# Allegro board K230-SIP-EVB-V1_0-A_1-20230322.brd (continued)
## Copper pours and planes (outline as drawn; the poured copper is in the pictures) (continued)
VDD_1V8 on POWER04: 65.21,78.17 50.04,93.34 32.38,93.34 31.75,92.71 31.75,89.28 31.62,89.15 13.21,89.15 7.75,83.69 7.75,49.02 8.38,48.39 23.62,48.39 23.88,48.13 23.88,33.4 23.62,33.15 16,33.15 14.86,32 14.86,16.64 15.62,15.88 32,15.88 35.43,19.3 35.43,43.05 35.69,43.31 74.8,43.31 75.06,43.05 75.06,8.89 71.63,5.46 7.75,5.46 0.89,12.32 0.89,108.71 1.4,109.22 7.87,109.22 8,109.35 8,135.38 8.13,135.51 71.25,135.51 74.3,132.46 74.3,78.49 73.98,78.17
VDD_3V3 on TOP: 8.64,91.57 8.76,91.69 9.65,91.69 9.78,91.57 9.78,89.92 9.65,89.79 8.76,89.79 8.64,89.92
VDD_3V3 on TOP: 21.72,28.7 21.72,31.24 22.1,31.62 22.1,32.13 22.23,32.26 23.11,32.26 23.24,32.13 23.24,30.86 22.86,30.48 22.86,28.7 22.73,28.57 21.84,28.57
VDD_3V3 on TOP: 17.02,130.94 17.02,127.38 17.14,127.25 19.56,127.25 19.68,127.13 19.68,125.09 19.56,124.97 14.61,124.97 14.48,125.09 14.48,125.98 15.49,127 15.49,130.94 15.62,131.06 16.89,131.06
VDD_3V3 on TOP: 30.61,45.97 30.86,46.23 30.86,46.74 30.99,46.86 32,46.86 32.13,46.74 32.13,45.21 31.75,44.83 31.75,42.93 31.62,42.8 30.73,42.8 30.61,42.93
VDD_3V3 on TOP: 28.57,28.7 28.57,31.24 28.96,31.62 28.96,32.13 29.08,32.26 29.59,32.26 29.72,32.13 29.72,28.7 29.59,28.57 28.7,28.57
VDD_3V3 on TOP: 46.74,131.32 51.18,131.32 51.31,131.19 51.31,129.16 51.18,129.03 46.86,129.03 46.61,129.29 46.61,131.19
VDD_3V3 on TOP: 44.07,46.23 44.07,46.74 44.2,46.86 45.09,46.86 45.21,46.74 45.21,45.47 44.83,45.09 44.83,43.18 44.7,43.05 43.69,43.05 43.56,43.18 43.56,45.72
VDD_3V3 on TOP: 18.8,19.81 18.92,19.68 18.92,17.91 18.8,17.78 15.37,17.78 15.24,17.91 15.24,19.68 15.37,19.81
VDD_3V3 on BOTTOM: 66.8,88.14 70.61,88.14 70.74,88.01 70.74,86.74 70.61,86.61 66.8,86.61 66.67,86.74 66.67,88.01
VDD_3V3 on BOTTOM: 56.45,131.06 56.45,119.32 60.58,115.19 60.58,112.27 60.33,112.01 55.5,112.01 53.09,114.43 34.42,114.43 34.16,114.68 34.16,119.76 34.42,120.02 49.02,120.02 49.4,120.4 49.4,131.06 49.53,131.19 56.32,131.19
VDD_3V3 on ART03: 78.74,91.82 78.74,73.03 78.61,72.9 71.25,72.9 71.12,73.03 71.12,78.11 61.47,87.76 61.47,98.81 58.93,101.35 58.93,113.67 59.05,113.79 71.12,113.79 71.25,113.67 71.25,99.31
VDD_3V3 on ART03: 9.14,89.79 10.99,91.63 10.99,100.65 26.67,116.33 35.69,116.33 35.81,116.46 35.81,127.13 35.69,127.25 17.91,127.25 17.78,127.13 17.78,119.13 2.41,103.76 2.41,89.92 2.54,89.79
VDD_3V3 on POWER04: 16.26,17.53 16,17.78 16,31.5 16.64,32.13 24.51,32.13 24.89,32.51 24.89,47.88 26.16,49.15 26.16,54.86 26.29,54.99 69.34,54.99 71.37,57.02 71.37,76.45 71.88,76.96 78.49,76.96 78.87,76.58 78.87,48.77 74.3,44.2 34.92,44.2 34.29,43.56 34.29,20.45 31.37,17.53
VDD_3V3_K210 on TOP: 10.79,25.02 10.79,24 10.67,23.88 8.51,23.88 8.38,24 8.38,25.02 8.51,25.15 10.67,25.15
VDD_3V3_USB on TOP: 18.8,17.53 18.92,17.4 18.92,15.75 18.8,15.62 15.11,15.62 14.99,15.75 14.99,17.4 15.11,17.53
VDD_5V on TOP (solid shape): 16.64,49.28 16.64,47.88 16.51,47.75 16.51,46.61 16.51,46.48 16.38,46.35 16.38,44.7 16.26,44.58 14.35,44.58 14.22,44.7 14.22,47.62 16,49.4 16.51,49.4
VDD_5V on TOP (solid shape): 46.23,27.81 46.23,26.42 46.1,26.29 46.1,25.15 46.1,25.02 45.97,24.89 45.97,23.37 45.85,23.24 44.07,23.24 43.81,23.5 43.81,26.16 45.59,27.94 46.1,27.94
VDD_5V on TOP (solid shape): 67.56,32.13 67.56,30.23 67.56,29.21 67.18,28.83 67.18,28.58 67.18,28.58 67.18,26.8 67.18,26.8 67.18,26.42 67.06,26.29 64.01,26.29 63.88,26.42 63.88,29.08 64.01,29.21 65.53,29.21 65.79,29.46 65.79,31.11 66.29,31.62 66.29,32.13 66.42,32.26 67.44,32.26
VDD_5V on TOP: 52.83,26.54 52.96,26.67 54.61,26.67 54.74,26.54 54.74,26.29 54.86,26.16 55.63,26.16 55.75,26.04 55.75,23.24 55.63,23.11 51.05,23.11 50.93,23.24 50.93,24 51.05,24.13 52.7,24.13 52.83,24.26
VDD_5V on TOP: 35.18,18.67 35.31,18.54 35.31,15.37 35.18,15.24 31.75,15.24 31.62,15.37 31.62,18.54 31.75,18.67
VDD_5V on TOP: 53.85,132.33 56.26,132.33 56.39,132.21 56.39,130.3 56.13,130.05 53.85,130.05 53.72,130.18 53.72,132.21
VDD_5V on TOP: 65.79,65.41 65.91,65.28 65.91,62.61 65.79,62.48 64.01,62.48 63.88,62.61 63.88,64.01 65.28,65.41
VDD_5V on TOP: 25.53,22.61 25.65,22.73 26.67,22.73 26.8,22.61 30.86,22.61 30.99,22.48 30.99,20.83 30.86,20.7 26.92,20.7 25.53,22.1
VDD_5V on TOP: 64.26,46.74 64.26,47.5 64.14,47.62 63.88,47.62 63.63,47.37 63.63,42.16 63.75,42.04 65.28,42.04 65.41,42.16 65.41,45.59
VDD_5V on TOP: 53.47,47.75 53.47,48.51 53.34,48.64 53.09,48.64 52.83,48.39 52.83,43.18 52.96,43.05 54.48,43.05 54.61,43.18 54.61,46.61
VDD_5V on TOP: 16.89,29.21 18.41,29.21 18.54,29.08 18.54,27.81 18.41,27.69 16.89,27.69 16.76,27.81 16.76,29.08
VDD_5V on BOTTOM: 1.4,7.49 1.14,7.75 1.14,34.16 2.16,35.18 8.51,35.18 10.16,36.83 10.16,52.32 10.41,52.58 18.03,52.58 18.16,52.45 18.16,31.75 18.86,31.05 51.37,31.05 51.94,31.62 51.94,46.35 52.07,46.48 66.29,46.48 67.06,47.24 67.06,55.5 63.88,58.67 63.88,64.64 64.01,64.77 68.83,64.77 71.69,67.63 71.69,88.27 69.6,90.36 69.6,106.68 64.77,111.51 64.77,124.33 61.09,128.02 61.09,129.92 61.21,130.05 63.85,130.05 67.28,126.62 67.28,112.81 72.07,108.01 72.07,93.92 77.09,88.9 77.09,78.99 76.71,78.61 76.71,66.17 72.52,61.98 72.52,40.89 68.01,36.39 68.01,28.13 60.33,20.45 48.9,20.45 43.43,14.99 32.64,14.99 32.38,14.73 32.38,7.62 32.26,7.49
VDD_5V on BOTTOM: 9.78,112.39 10.67,111.51 10.67,111 10.54,110.87 9.27,110.87 8.26,111.89 8.26,117.73 8.38,117.86 9.65,117.86 9.78,117.73
VDD_5V on ART03: 61.91,128.59 61.59,128.27 51.94,128.27 46.35,133.86 22.61,133.86 13.59,124.84 13.59,116.2 13.21,115.82 6.22,115.82 5.97,116.08 5.97,128.14 16.26,138.43 60.2,138.43 61.91,136.72
VDD_5V_O on TOP: 46.1,132.97 46.1,134.75 47.75,136.4 54.61,136.4 56.39,134.62 56.39,133.22 56.26,133.1 52.32,133.1 51.69,132.46 46.61,132.46
VDD_5V_O on TOP: 7.11,90.68 6.99,90.81 5.84,90.81 3.68,92.96 3.68,106.68 4.19,107.19 8,107.19 10.41,109.6 10.41,122.68 10.29,122.81 7.62,122.81 7.49,122.68 7.49,112.14 5.71,110.36 2.16,110.36 1.4,109.6 1.4,90.3 2.92,88.77 6.99,88.77 7.11,88.9
VDD_5V_O on BOTTOM: 51.69,138.3 51.69,134.49 51.56,134.37 49.15,134.37 49.02,134.49 49.02,136.4 48.9,136.53 35.94,136.53 27.81,128.4 9.91,128.4 8.26,126.75 8.26,119.51 8.13,119.38 4.45,119.38 4.32,119.51 4.32,128.4 8.89,132.97 26.67,132.97 32.38,138.68 51.31,138.68
(no net) on TOP: 44.45,35.05 44.45,38.35 44.07,38.73 41.02,38.73 40.89,38.86 40.89,40.13 41.02,40.26 46.86,40.26 46.99,40.13 46.99,35.05 46.86,34.92 44.58,34.92
(no net) on TOP: 46.86,23.24 46.74,23.37 46.74,25.02 46.61,25.15 46.61,27.69 46.86,27.94 46.86,29.21 46.74,29.34 44.2,29.34 44.07,29.46 44.07,30.23 44.2,30.35 47.37,30.35 47.5,30.48 47.5,40.89 47.62,41.02 55.88,41.02 56.01,40.89 56.01,38.48 55.88,38.35 53.85,38.35 53.47,38.73 50.16,38.73 50.04,38.61 50.04,29.34 49.53,28.83 49.53,24.38 48.39,23.24
(no net) on TOP: 12.7,56.01 12.7,57.15 12.57,57.28 11.43,57.28 11.3,57.4 11.3,58.8 11.43,58.93 14.35,58.93 14.48,58.8 14.48,56.01 14.35,55.88 12.83,55.88
(no net) on TOP: 14.86,56.52 14.86,59.82 14.48,60.2 11.43,60.2 11.3,60.33 11.3,61.85 11.43,61.98 17.27,61.98 17.4,61.85 17.4,56.52 17.27,56.39 14.99,56.39
(no net) on TOP: 43.05,32.26 43.05,33.02 42.93,33.15 42.42,33.15 42.29,33.27 42.29,34.04 42.42,34.16 43.81,34.16 43.94,34.04 43.94,32.26 43.81,32.13 43.18,32.13
(no net) on TOP: 13.46,53.72 13.46,54.48 13.34,54.61 12.83,54.61 12.7,54.74 12.7,55.5 12.83,55.63 14.22,55.63 14.35,55.5 14.35,53.72 14.22,53.59 13.59,53.59
(no net) on TOP: 14.73,54.99 14.86,55.12 17.4,55.12 17.53,54.99 17.53,53.09 17.4,52.96 16.26,52.96 15.62,53.59 14.86,53.59 14.73,53.72
(no net) on TOP: 11.18,57.02 11.81,57.02 11.94,56.9 11.94,53.85 11.81,53.72 6.86,53.72 6.73,53.85 6.73,58.8 6.86,58.93 10.79,58.93 10.92,58.8 10.92,57.28
(no net) on TOP: 67.94,32.51 64.9,32.51 64.77,32.64 64.77,33.4 64.9,33.53 67.94,33.53 68.07,33.66 68.07,36.58 68.2,36.7 70.23,36.7 70.36,36.58 70.36,26.42 70.23,26.29 68.58,26.29 68.45,26.42 68.45,28.96 68.07,29.34 68.07,32.38
(no net) on TOP: 16.51,49.4 16.64,49.28 16.64,47.88 16.51,47.75 16.51,46.48 16.38,46.35 16.38,44.7 16.26,44.58 14.35,44.58 14.22,44.7 14.22,47.62 16,49.4
(no net) on TOP: 63.25,38.86 63.12,38.99 63.12,40.77 63.25,40.89 67.44,40.89 67.56,40.77 67.56,38.99 67.44,38.86
(no net) on TOP: 68.07,38.1 68.07,40.77 68.2,40.89 75.82,40.89 75.95,40.77 75.95,38.1 75.82,37.97 68.2,37.97
(no net) on TOP: 40.77,35.56 41.4,35.56 41.53,35.43 41.53,32.26 41.4,32.13 39.62,32.13 39.5,32.26 39.5,36.45 39.62,36.58 40.51,36.58 40.64,36.45 40.64,35.69
(no net) on TOP: 42.29,34.54 42.29,35.69 42.16,35.81 41.02,35.81 40.89,35.94 40.89,37.34 41.02,37.47 43.94,37.47 44.07,37.34 44.07,34.54 43.94,34.42 42.42,34.42
(no net) on TOP: 67.56,33.91 67.44,33.78 66.42,33.78 66.29,33.91 66.29,34.92 65.91,35.31 65.91,38.48 66.04,38.61 67.44,38.61 67.56,38.48
(no net) on TOP: 63.88,29.08 64.01,29.21 65.53,29.21 65.79,29.46 65.79,31.11 66.29,31.62 66.29,32.13 66.42,32.26 67.44,32.26 67.56,32.13 67.56,29.21 67.18,28.83 67.18,26.42 67.06,26.29 64.01,26.29 63.88,26.42
(no net) on TOP: 44.32,33.53 44.45,33.66 46.99,33.66 47.12,33.53 47.12,31.62 46.99,31.5 45.85,31.5 45.21,32.13 44.45,32.13 44.32,32.26
(no net) on TOP: 46.1,27.94 46.23,27.81 46.23,26.42 46.1,26.29 46.1,25.02 45.97,24.89 45.97,23.37 45.85,23.24 44.07,23.24 43.81,23.5 43.81,26.16 45.59,27.94
INA226_0V8+ on TOP (solid shape): 17.4,61.85 17.4,60.07 17.4,60.07 17.4,59.05 17.4,59.05 17.4,58.8 17.4,58.8 17.4,57.78 17.4,57.78 17.4,56.52 17.27,56.39 14.99,56.39 14.86,56.52 14.86,59.82 14.48,60.2 11.43,60.2 11.3,60.33 11.3,61.85 11.43,61.98 17.27,61.98
INA226_0V8- on TOP (solid shape): 14.48,58.8 14.48,56.01 14.35,55.88 12.83,55.88 12.7,56.01 12.7,57.15 12.57,57.28 11.43,57.28 11.3,57.4 11.3,58.8 11.43,58.93 14.35,58.93
INA226_1V8IO+ on TOP: 66.29,75.82 66.04,75.56 66.04,71.88 65.91,71.75 63.5,71.75 63.37,71.88 63.37,78.61 63.5,78.74 66.17,78.74 66.29,78.61
INA226_1V8IO- on TOP: 61.85,69.72 61.72,69.85 61.72,74.55 60.45,75.82 60.45,77.72 60.58,77.85 61.98,77.85 62.1,77.72 62.1,76.07 63.12,75.06 63.12,69.85 62.99,69.72
INA226_AVDDMIPI+ on TOP: 16,33.78 15.37,33.78 15.24,33.91 15.24,34.8 14.86,35.18 14.86,37.34 14.48,37.72 14.48,39.37 14.61,39.5 16.38,39.5 16.51,39.37 16.51,37.85 16.13,37.47 16.13,33.91
INA226_AVDDMIPI- on TOP: 16.51,42.8 16.51,40.89 16.38,40.77 14.61,40.77 14.22,41.15 13.34,41.15 13.21,41.27 13.21,42.8 13.34,42.93 16.38,42.93
INA226_CORE0+ on TOP (solid shape): 46.99,40.13 46.99,38.61 46.99,37.59 46.99,37.34 46.99,36.32 46.99,35.05 46.86,34.92 44.58,34.92 44.45,35.05 44.45,38.35 44.07,38.73 41.02,38.73 40.89,38.86 40.89,40.13 41.02,40.26 46.86,40.26
INA226_CORE0- on TOP (solid shape): 44.07,37.34 44.07,34.54 43.94,34.42 42.42,34.42 42.29,34.54 42.29,35.69 42.16,35.81 41.02,35.81 40.89,35.94 40.89,37.34 41.02,37.47 43.94,37.47
INA226_CORE+ on TOP: 53.85,54.1 53.72,53.98 48.9,53.98 48.77,54.1 48.77,58.93 48.9,59.05 53.72,59.05 53.85,58.93
INA226_CORE- on TOP: 48.9,61.72 49.02,61.85 54.86,61.85 54.99,61.72 54.99,60.45 54.86,60.33 49.02,60.33 48.9,60.45
INA226_DDR_CORE+ on TOP: 23.5,48.39 23.37,48.51 23.37,49.4 22.99,49.78 22.99,51.94 22.73,52.2 22.73,54.48 22.86,54.61 24.51,54.61 24.64,54.48 24.64,52.32 24.26,51.94 24.26,48.51 24.13,48.39
INA226_DDR_CORE- on TOP: 24.26,55.88 22.86,55.88 22.73,56.01 22.73,59.82 22.86,59.94 24.26,59.94 24.38,59.82 24.38,56.01
INA226_DDR_DRAM+ on TOP: 44.83,48.39 44.2,48.39 44.07,48.51 44.07,49.4 43.69,49.78 43.69,52.2 43.05,52.83 43.05,54.48 43.18,54.61 45.21,54.61 45.34,54.48 45.34,52.83 44.96,52.45 44.96,48.51
INA226_DDR_DRAM- on TOP: 43.18,55.88 43.05,56.01 43.05,59.82 43.18,59.94 45.34,59.94 45.47,59.82 45.47,56.01 45.34,55.88
INA226_DDR_IO0+ on TOP: 35.69,31.75 35.69,35.94 37.21,37.47 38.86,37.47 38.99,37.34 38.99,36.07 38.86,35.94 37.85,35.94 37.47,35.56 37.47,31.75 37.34,31.62 35.81,31.62
INA226_DDR_IO0- on TOP: 38.73,38.99 36.7,38.99 36.45,39.24 35.69,39.24 35.56,39.37 35.56,40.89 35.69,41.02 38.73,41.02 38.86,40.89 38.86,39.12
INA226_DDR_IO+ on TOP: 37.47,53.09 37.47,51.82 37.08,51.44 37.08,48.77 36.96,48.64 35.94,48.64 35.81,48.77 35.81,52.2 35.05,52.96 35.05,54.74 35.18,54.86 37.08,54.86 37.34,55.12 38.61,55.12 38.73,54.99 38.73,53.34 38.61,53.21 37.59,53.21
INA226_DDR_IO- on TOP: 35.31,59.94 36.58,59.94 36.7,59.82 36.7,57.78 37.08,57.4 38.48,57.4 38.61,57.28 38.61,55.88 38.48,55.75 35.31,55.75 35.18,55.88 35.18,59.82
INA226_KPU0+ on TOP: 53.59,37.47 53.98,37.85 56.01,37.85 56.39,37.47 58.29,37.47 58.42,37.34 58.42,33.27 58.29,33.15 50.93,33.15 50.8,33.27 50.8,37.34 50.93,37.47
INA226_KPU0- on TOP: 56.26,40.89 56.39,41.02 60.96,41.02 61.09,40.89 61.09,38.86 60.96,38.73 56.39,38.73 56.26,38.86
INA226_KPU+ on TOP: 64.39,53.98 59.69,53.98 59.56,54.1 59.56,58.93 59.69,59.05 63.25,59.05 63.37,58.93 63.37,56.9 64.52,55.75 64.52,54.1
INA226_KPU- on TOP: 59.69,61.85 59.82,61.98 65.66,61.98 65.79,61.85 65.79,60.58 65.66,60.45 61.34,60.45 60.71,59.82 59.82,59.82 59.69,59.94
INA226_MIPI1V8+ on TOP: 30.99,48.39 30.86,48.51 30.86,49.4 30.48,49.78 30.48,52.07 29.84,52.7 27.18,52.7 27.05,52.83 27.05,54.48 27.18,54.61 31.62,54.61 31.75,54.48 31.75,48.51 31.62,48.39
INA226_MIPI1V8- on TOP: 34.54,56.9 34.67,56.77 34.67,55.5 34.54,55.37 29.46,55.37 28.96,55.88 27.05,55.88 26.67,55.5 25.4,55.5 25.27,55.63 25.27,56.77 25.4,56.9 26.42,56.9 26.92,57.4 29.08,57.4 29.59,56.9
INA226_PLL+ on TOP: 56.26,65.02 57.15,65.91 57.4,65.91 57.53,65.79 57.53,64.52 57.02,64.01 52.2,64.01 52.07,64.14 52.07,65.79 52.2,65.91 53.98,65.91 54.86,65.02
INA226_PLL- on TOP: 52.2,67.44 52.07,67.56 52.07,69.98 52.2,70.1 54.48,70.1 54.61,69.98 54.61,67.56 54.48,67.44
INA226_PLL- on BOTTOM: 53.85,68.2 53.72,68.07 52.2,68.07 52.07,68.2 52.07,69.98 52.2,70.1 53.72,70.1 53.85,69.98
INA226_USB+ on TOP: 14.48,23.11 14.73,22.86 18.41,22.86 18.54,22.73 18.54,20.32 18.41,20.19 10.41,20.19 10.29,20.07 10.29,16.38 10.16,16.26 8.13,16.26 7.94,16.45 7.94,22.03 9.02,23.11
INA226_USB- on TOP: 11.3,15.88 11.3,19.56 11.43,19.68 14.35,19.68 14.48,19.56 14.48,15.88 14.35,15.75 11.43,15.75
MICBIAS on BOTTOM: 40.01,87.25 39.24,87.25 39.12,87.38 39.12,90.17 39.37,90.42 40.39,90.42 40.64,90.17 40.64,89.92 40.13,89.41 40.13,87.38
NVCC_SD on TOP: 13.72,125.98 13.72,124.97 19.75,118.94 19.75,109.03 19.56,108.84 15.11,108.84 11.18,112.78 11.18,125.98 11.3,126.11 13.59,126.11
NVCC_SD on BOTTOM: 14.1,113.54 13.97,113.67 13.21,113.67 13.08,113.54 13.08,112.39 12.19,111.51 12.19,111 12.32,110.87 13.97,110.87 14.1,111
RTC_1V8 on TOP (solid shape): 75.95,40.77 75.95,38.1 75.82,37.97 68.2,37.97 68.07,38.1 68.07,39.88 68.07,40.77 68.2,40.89 75.82,40.89
RTC_1V8 on ART03: 78.74,29.34 78.74,26.42 78.49,26.16 73.53,26.16 73.41,26.29 73.41,40.77 73.53,40.89 75.82,40.89 75.95,40.77 75.95,32.13
USB0_OTG_VBUS on TOP: 73.28,70.48 70.87,70.48 70.36,69.98 70.36,64.52 70.87,64.01 70.87,63.12 70.74,62.99 69.22,62.99 69.09,63.12 69.09,70.23 69.98,71.12 73.15,71.12 74.42,72.39 74.42,74.17 73.15,75.44 70.87,75.44 70.23,76.07 70.23,76.45 70.36,76.58 70.99,76.58 71.5,76.07 73.15,76.07 74.93,74.3 74.93,72.14
VAA_DDR on TOP: 30.35,37.85 30.23,37.97 30.23,40.89 30.35,41.02 32.51,41.02 32.64,40.89 32.64,38.1 32.38,37.85
VAA_DDR on TOP: 34.8,60.07 34.92,59.94 34.92,57.53 34.8,57.4 32.64,57.4 32.51,57.53 32.51,59.94 32.64,60.07
VAA_DDR on BOTTOM: 34.42,64.39 34.42,70.87 34.54,70.99 36.2,70.99 36.32,70.87 36.32,58.17 32.51,54.36 32.51,39.5 32.26,39.24 28.83,39.24 28.7,39.37 28.7,54.48 34.04,59.82 34.04,64.01
N22175184 on TOP: 68.07,8.64 67.94,8.51 64.14,8.51 64.01,8.64 64.01,14.1 64.14,14.22 67.94,14.22 68.07,14.1
N22177946 on TOP: 62.36,51.31 62.48,51.44 64.64,51.44 64.77,51.31 64.77,48.9 63.63,47.75 63.37,47.75 62.36,48.77
N22185516 on TOP: 22.86,33.78 22.23,33.78 22.1,33.91 22.1,34.8 21.72,35.18 21.72,38.48 21.84,38.61 22.86,38.61 22.99,38.48 22.99,33.91
N22186056 on TOP: 29.72,33.78 29.08,33.78 28.96,33.91 28.96,34.8 28.57,35.18 28.57,38.61 28.7,38.73 29.72,38.73 29.84,38.61 29.84,33.91
N22192931 on TOP: 14.86,28.32 14.86,31.24 15.24,31.62 15.24,32.13 15.37,32.26 15.88,32.26 16,32.13 16,28.32 15.88,28.19 14.99,28.19
N22217278 on TOP: 51.56,52.32 51.69,52.45 53.85,52.45 53.98,52.32 53.98,49.91 52.83,48.77 52.58,48.77 51.56,49.78
N22277860 on TOP: 71.88,66.55 73.41,66.55 73.53,66.42 73.53,59.94 72.77,59.18 71.88,59.18 71.75,59.31 71.75,66.42
N22445414 on TOP (solid shape): 47.12,33.53 47.12,31.62 46.99,31.5 45.85,31.5 45.21,32.13 44.45,32.13 44.32,32.26 44.32,33.53 44.45,33.66 46.99,33.66
N22458931 on TOP (solid shape): 17.53,54.99 17.53,53.09 17.4,52.96 16.26,52.96 15.62,53.59 14.86,53.59 14.73,53.72 14.73,54.99 14.86,55.12 17.4,55.12
N22477358 on TOP: 66.29,71.12 66.42,70.99 66.42,69.09 66.29,68.96 65.53,68.96 64.9,69.6 63.63,69.6 63.5,69.72 63.5,70.99 63.63,71.12
N22506626 on TOP: 73.79,101.85 73.28,101.35 71.75,101.35 71.63,101.47 71.63,101.96 71.7,102.03 73.2,102.03 74.55,103.38 74.55,104.95 73.2,106.3 71.73,106.3 71.68,106.35 71.68,106.88 71.73,106.93 73.23,106.93 73.61,106.55 74.68,106.55 74.8,106.68 74.8,108.97 74.17,109.6 72.39,109.6 71.12,108.33 66.67,108.33 66.55,108.46 66.55,110.74 66.74,110.93 74.61,110.93 76.2,109.35 76.2,103.25 74.8,101.85
N22537740 on TOP: 52.83,29.72 52.83,32.13 52.96,32.26 56.13,32.26 56.26,32.13 56.26,28.57 56.13,28.45 54.1,28.45
N22561654 on TOP: 19.81,22.99 19.94,23.11 21.84,23.11 21.97,22.99 21.97,22.35 21.34,21.72 21.34,20.45 21.21,20.32 19.94,20.32 19.81,20.45
N22848145 on TOP (solid shape): 67.56,38.48 67.56,36.58 67.56,35.56 67.56,33.91 67.44,33.78 66.42,33.78 66.29,33.91 66.29,34.92 65.91,35.31 65.91,38.48 66.04,38.61 67.44,38.61

Small or netless copper shapes (teardrops, artwork), in the pictures only: 15 on TOP

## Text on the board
Ref Des/Silkscreen Bottom: GND | GPIO35 | VDD_5V | RTC_INT2 | GPIO37 | GPIO33 | GPIO32 | UART4_RXD_3V3 | UART4_TXD_3V3 | GPIO36 | GPIO34 | EN_DDR_K210 | EN_CORE_K210 | UART0_RXD | GPIO39 | HP_INSERT_DET | UART0_TXD | GPIO8 | IIC4_SDA | IIC4_SCL | SD2_DET | VSYNC0 | HSYNC0 | GPIO38 | VPWM_CORE | VPWM_KPU | GPIO7 | SDIO_DET | SYS_SW | PW_EN | OUT0 | NC | INT4 | RTC_1V8 | INT2 | INT1 | INT0 | SYS_ON_OFF
User.Comments: CR_UNNAMED_1
Ref Des/Silkscreen Top: NVCC-SD | GND | DSI_D3_P | DSI_D2_N | DSI_D0_P | DSI_CLK0_P | DSI_D1_P | 0V8_DDR_CORE | MIPI-1V8 | BOOT1 | BOOT0 | 0 | 1 | NOR FLASH | MMC0 | 3V3 | 5V | NAND FLASH | TF CARD | 1V1_DDR | MMC1 | VBUS-CHARGE | 1V8_CODEC | A | 1V8_ADC | 1V8_USB | 1V1_DRAM | B | 0V8_CPU | CTRL0 | UART0-RXD_3V3 | TXD_3V3 | UART0/4 | H | L | USB | 0V8_PLL | 1V8 | TCK | TDO | TDI | TMS | RST | NC | VDD_0V8 | MIPI_0V8 | 3V3_USB | CSI0_D3_P | CSI0_CLK1_P | CSI0_D2_N | CSI0_D0_P | CSI0_CLK0_P | CSI0_D1_P | 1V8DDR | CSI0_D5_N | CSI0_D4_P | VAA | CSI0_CLK2_N | 0V8_KPU | RTC-1V8 | RESET | K230-SIP-EVB-V1.0-A.1 | 2023-03-22 | DC 5V | : | OFF | ON
User.22: FIGURE | SIZE | 8.0 | 10.0 | 30.0 | 40.0 | 45.0 | 55.0 | 115.0 | 125.0 | 24.0 | 28.0 | 48.0 | 60.0 | 50.0x30.0 | 70.0x30.0 | 70.0x40.0 | DRILL CHART: TOP to BOTTOM | ALL UNITS ARE IN MILS | PLATED | NON-PLATED | QTY | 224 | 1117 | 3 | 104 | 2 | 4 | 6 | 1
